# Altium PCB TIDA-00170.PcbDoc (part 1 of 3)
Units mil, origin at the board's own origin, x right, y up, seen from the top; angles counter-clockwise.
Board outline 3780 x 2000 mil, 4 copper layers (Top Layer, L2_GND-PLANE, L3_PWR-PLANE, Bottom Layer), stack 90 mil thick; 275 components, 132 nets, 768 pads, 262 vias.
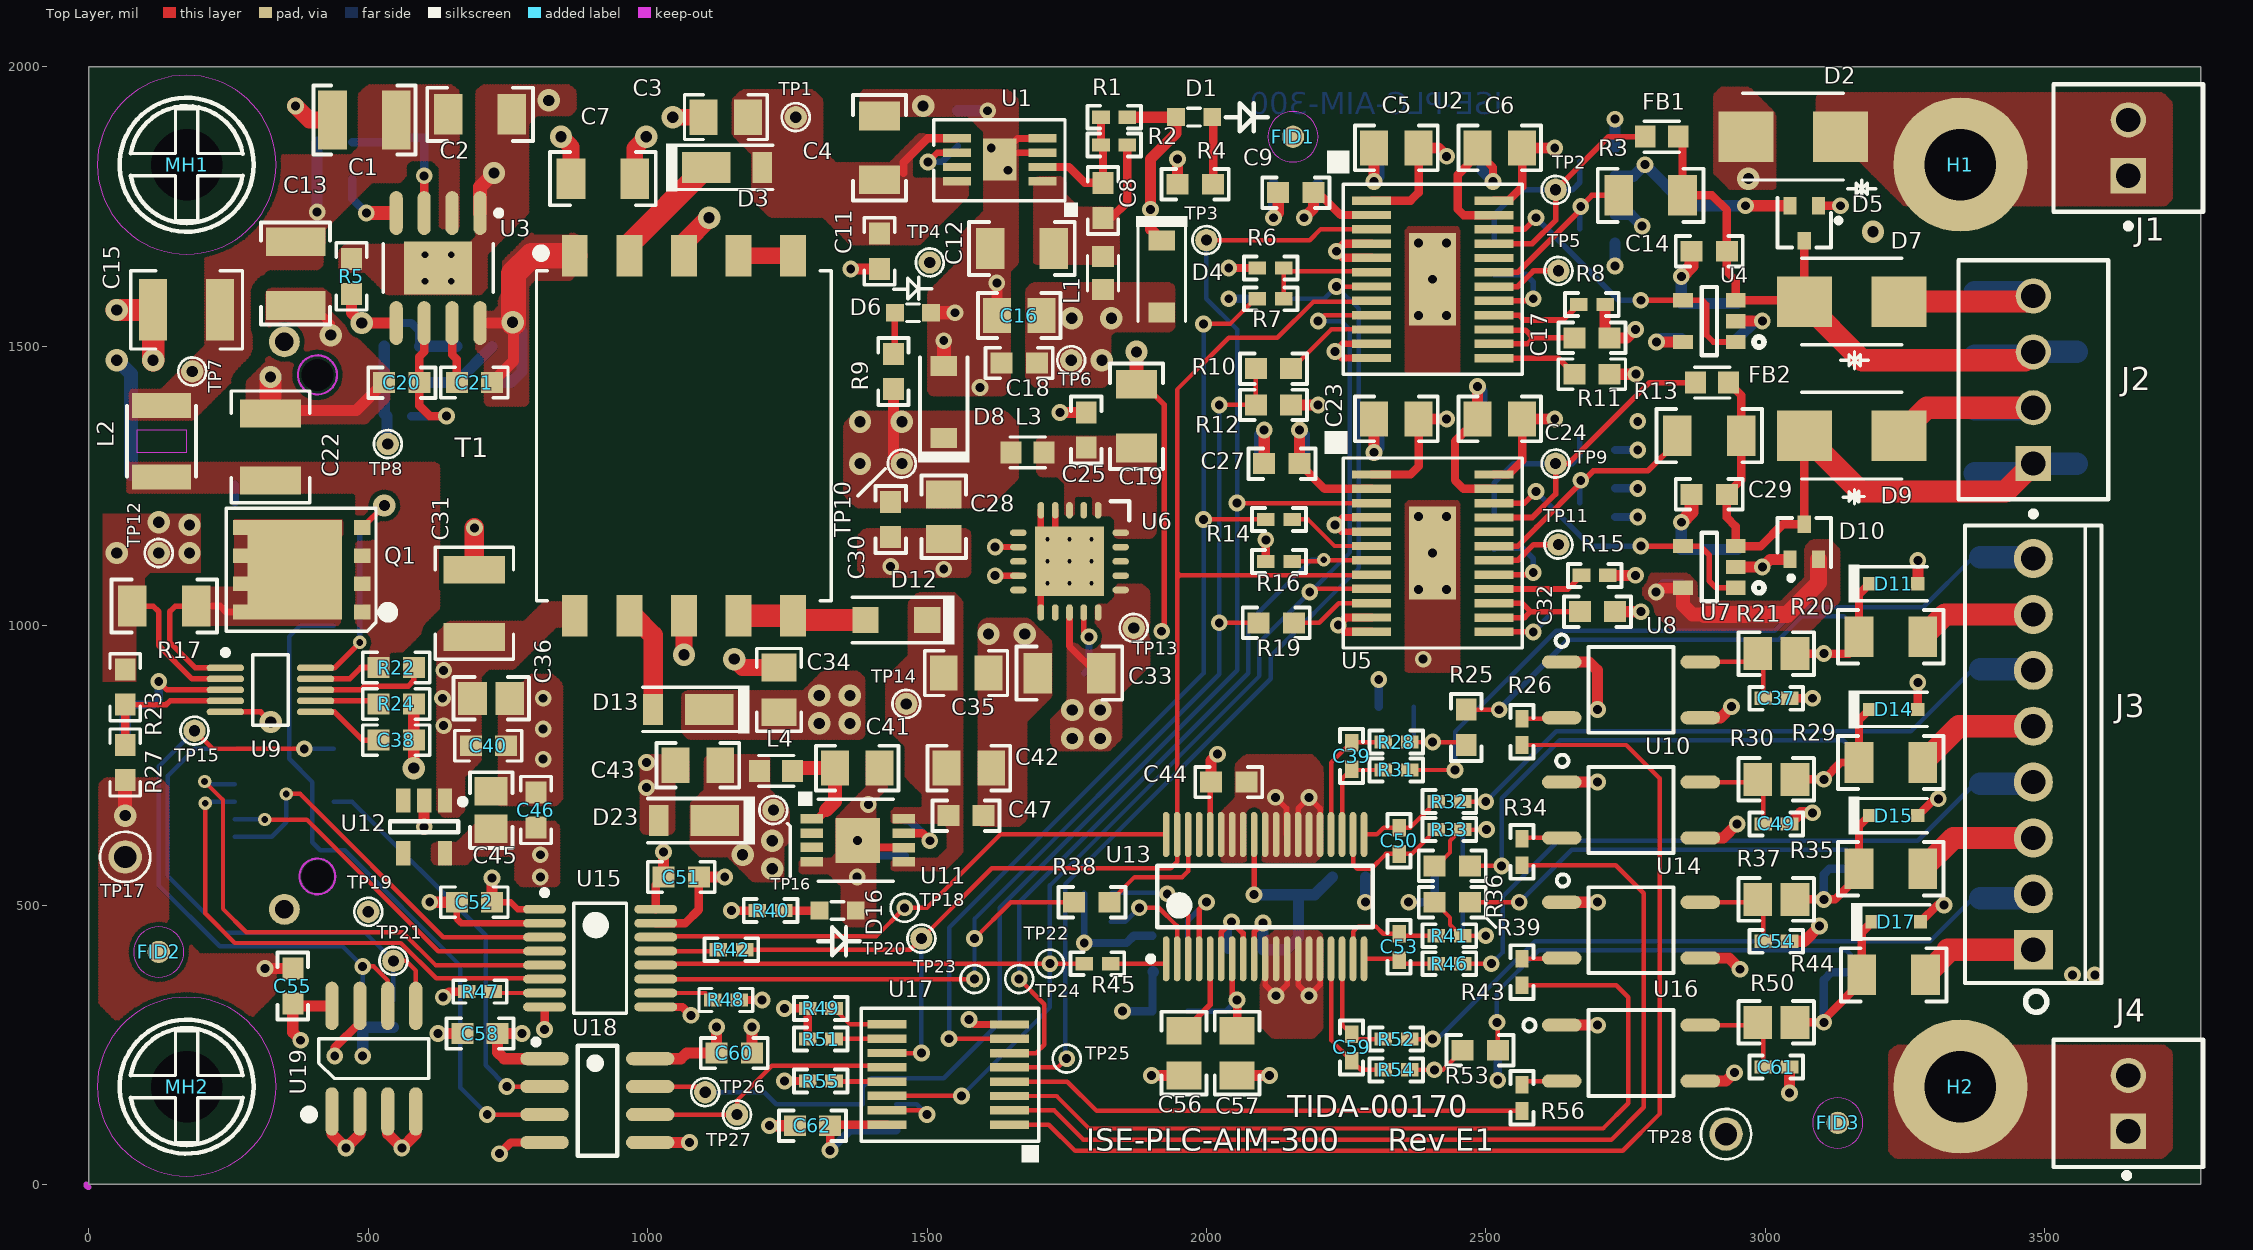
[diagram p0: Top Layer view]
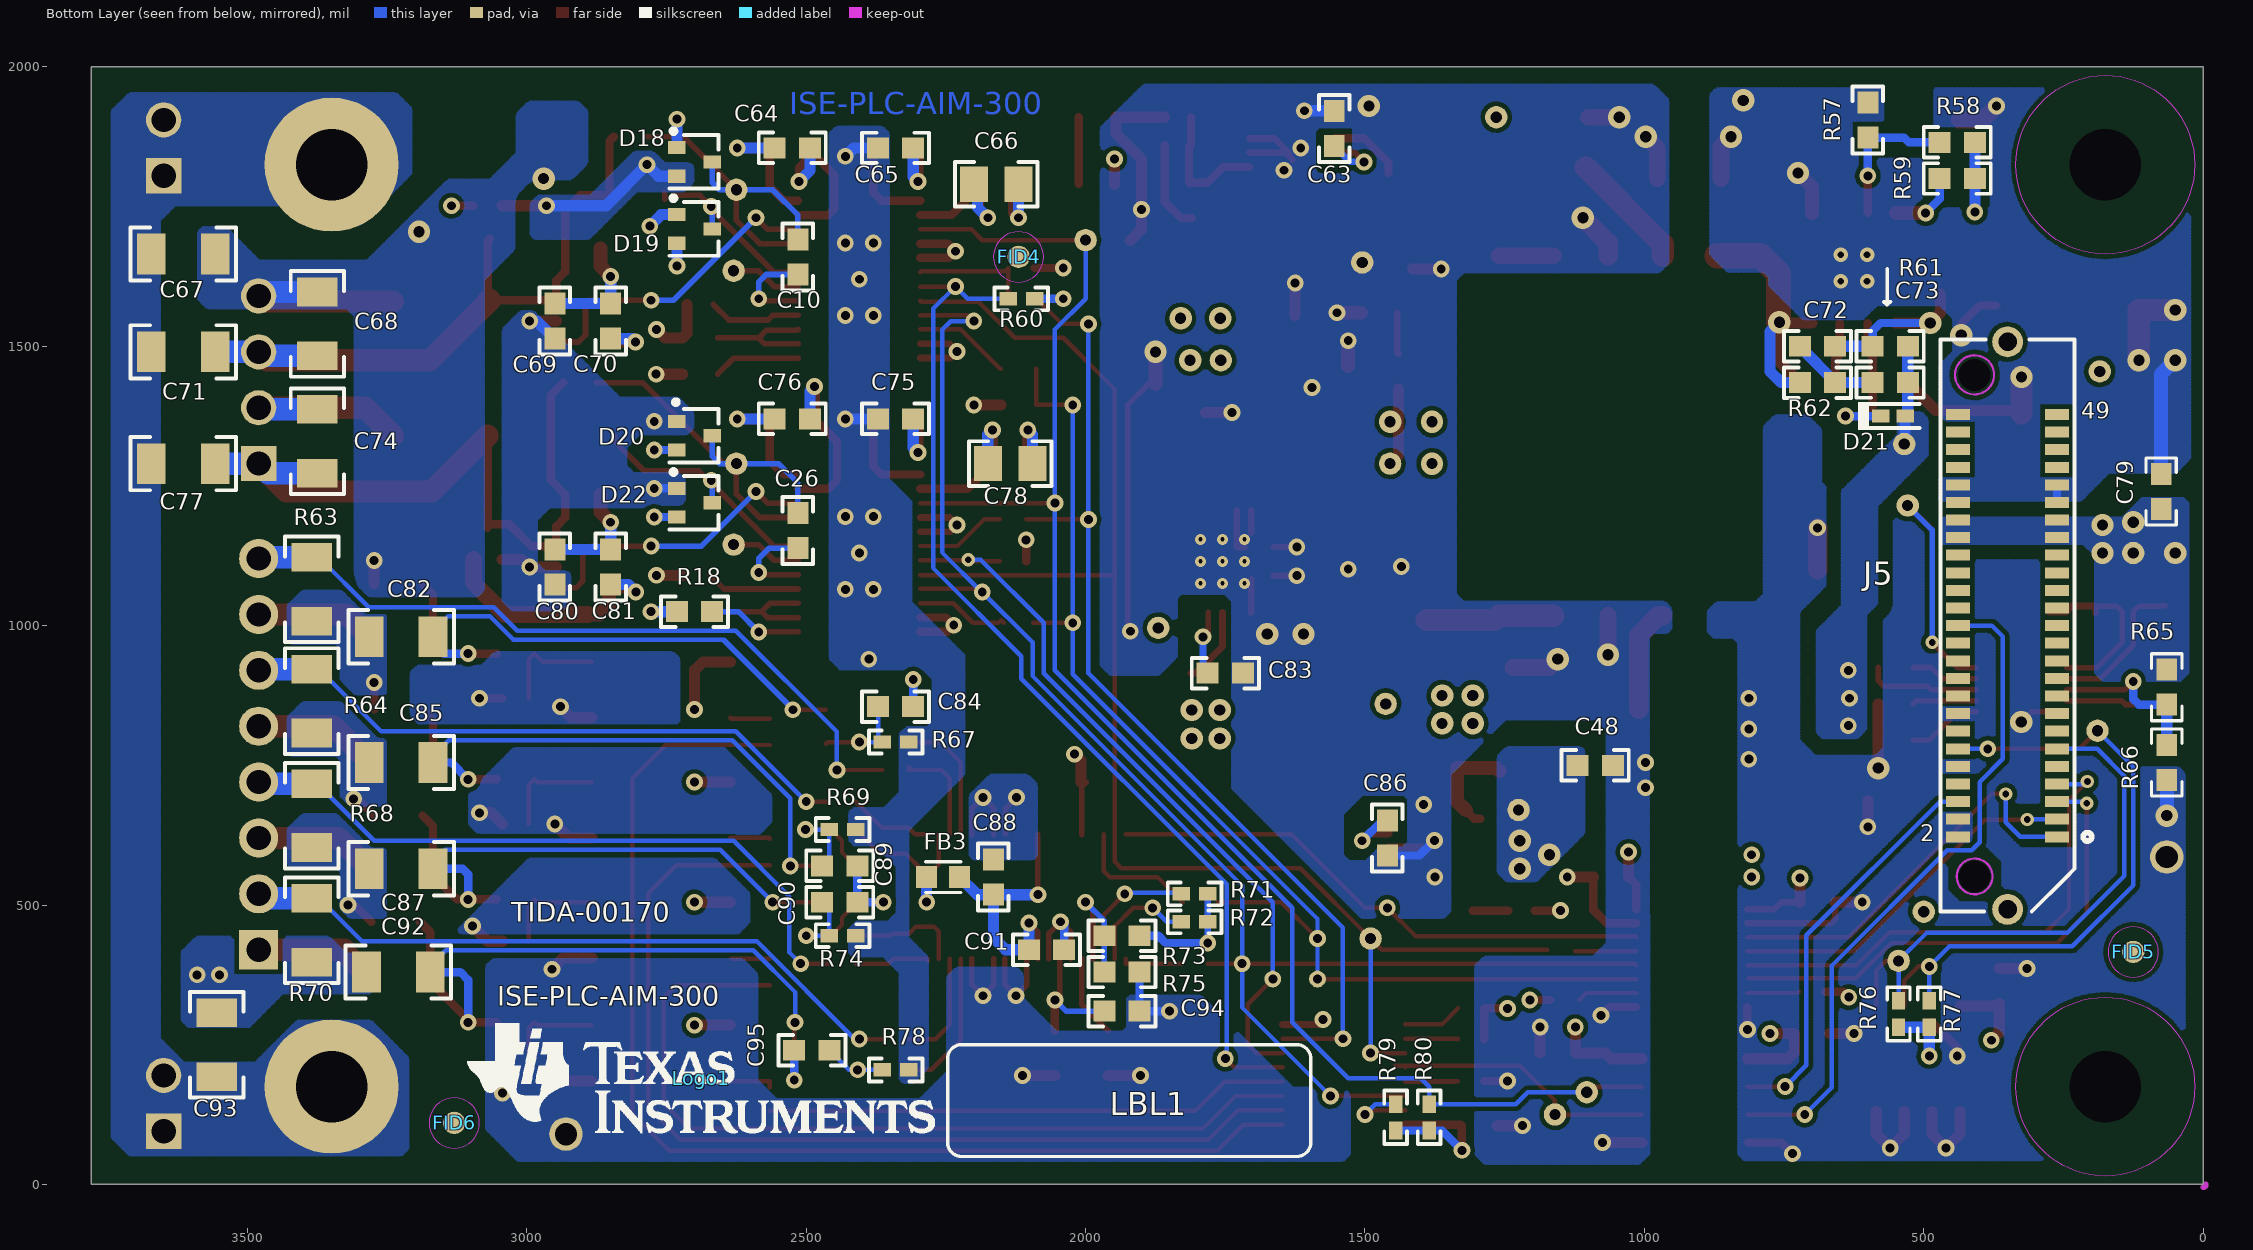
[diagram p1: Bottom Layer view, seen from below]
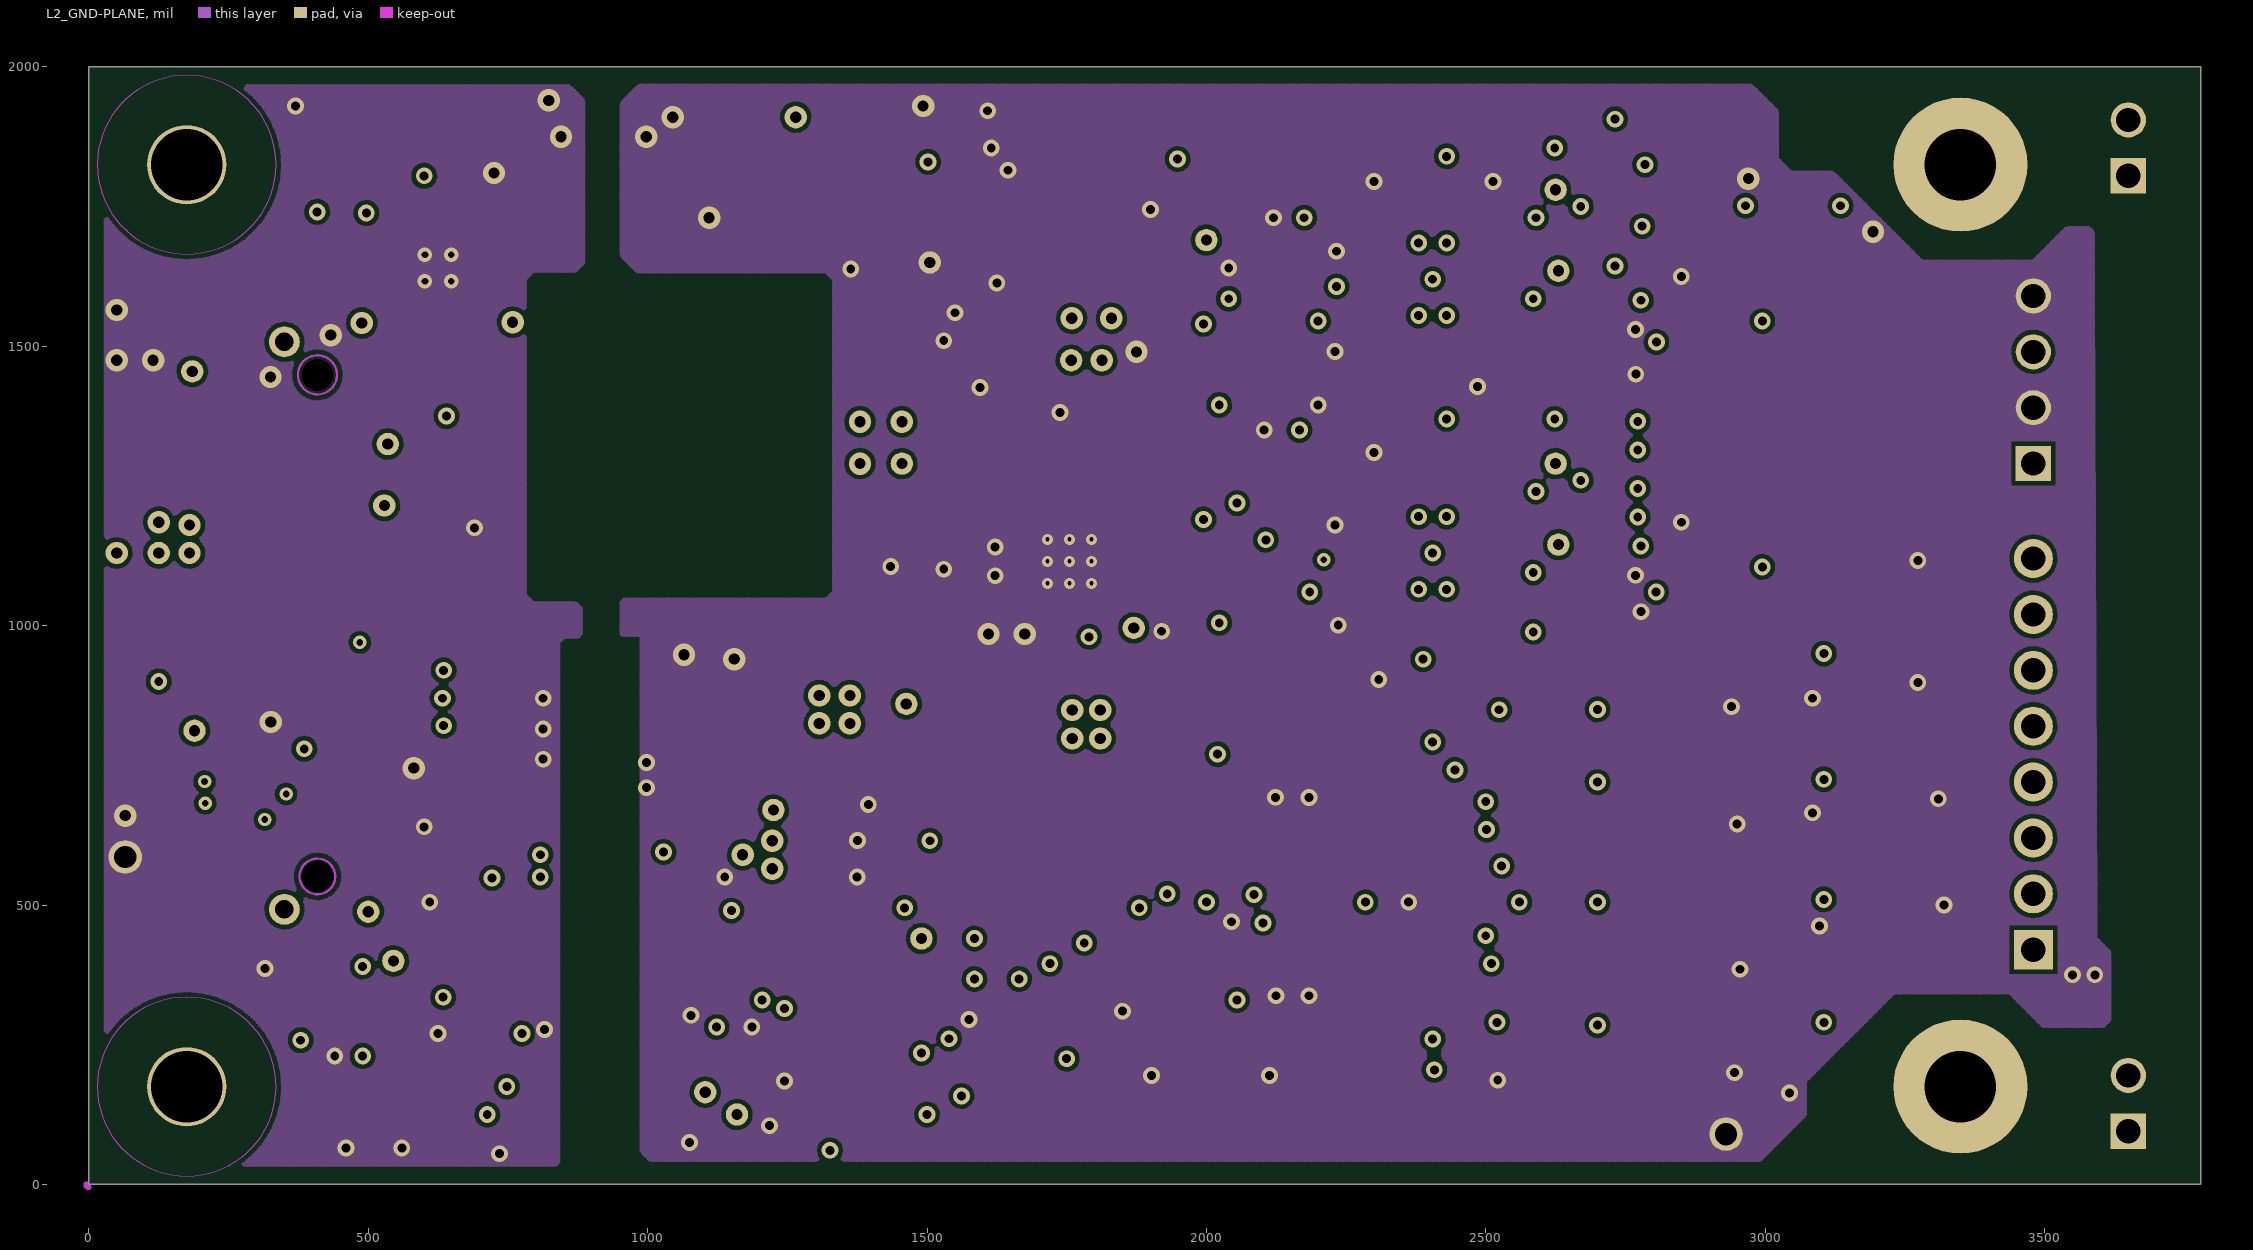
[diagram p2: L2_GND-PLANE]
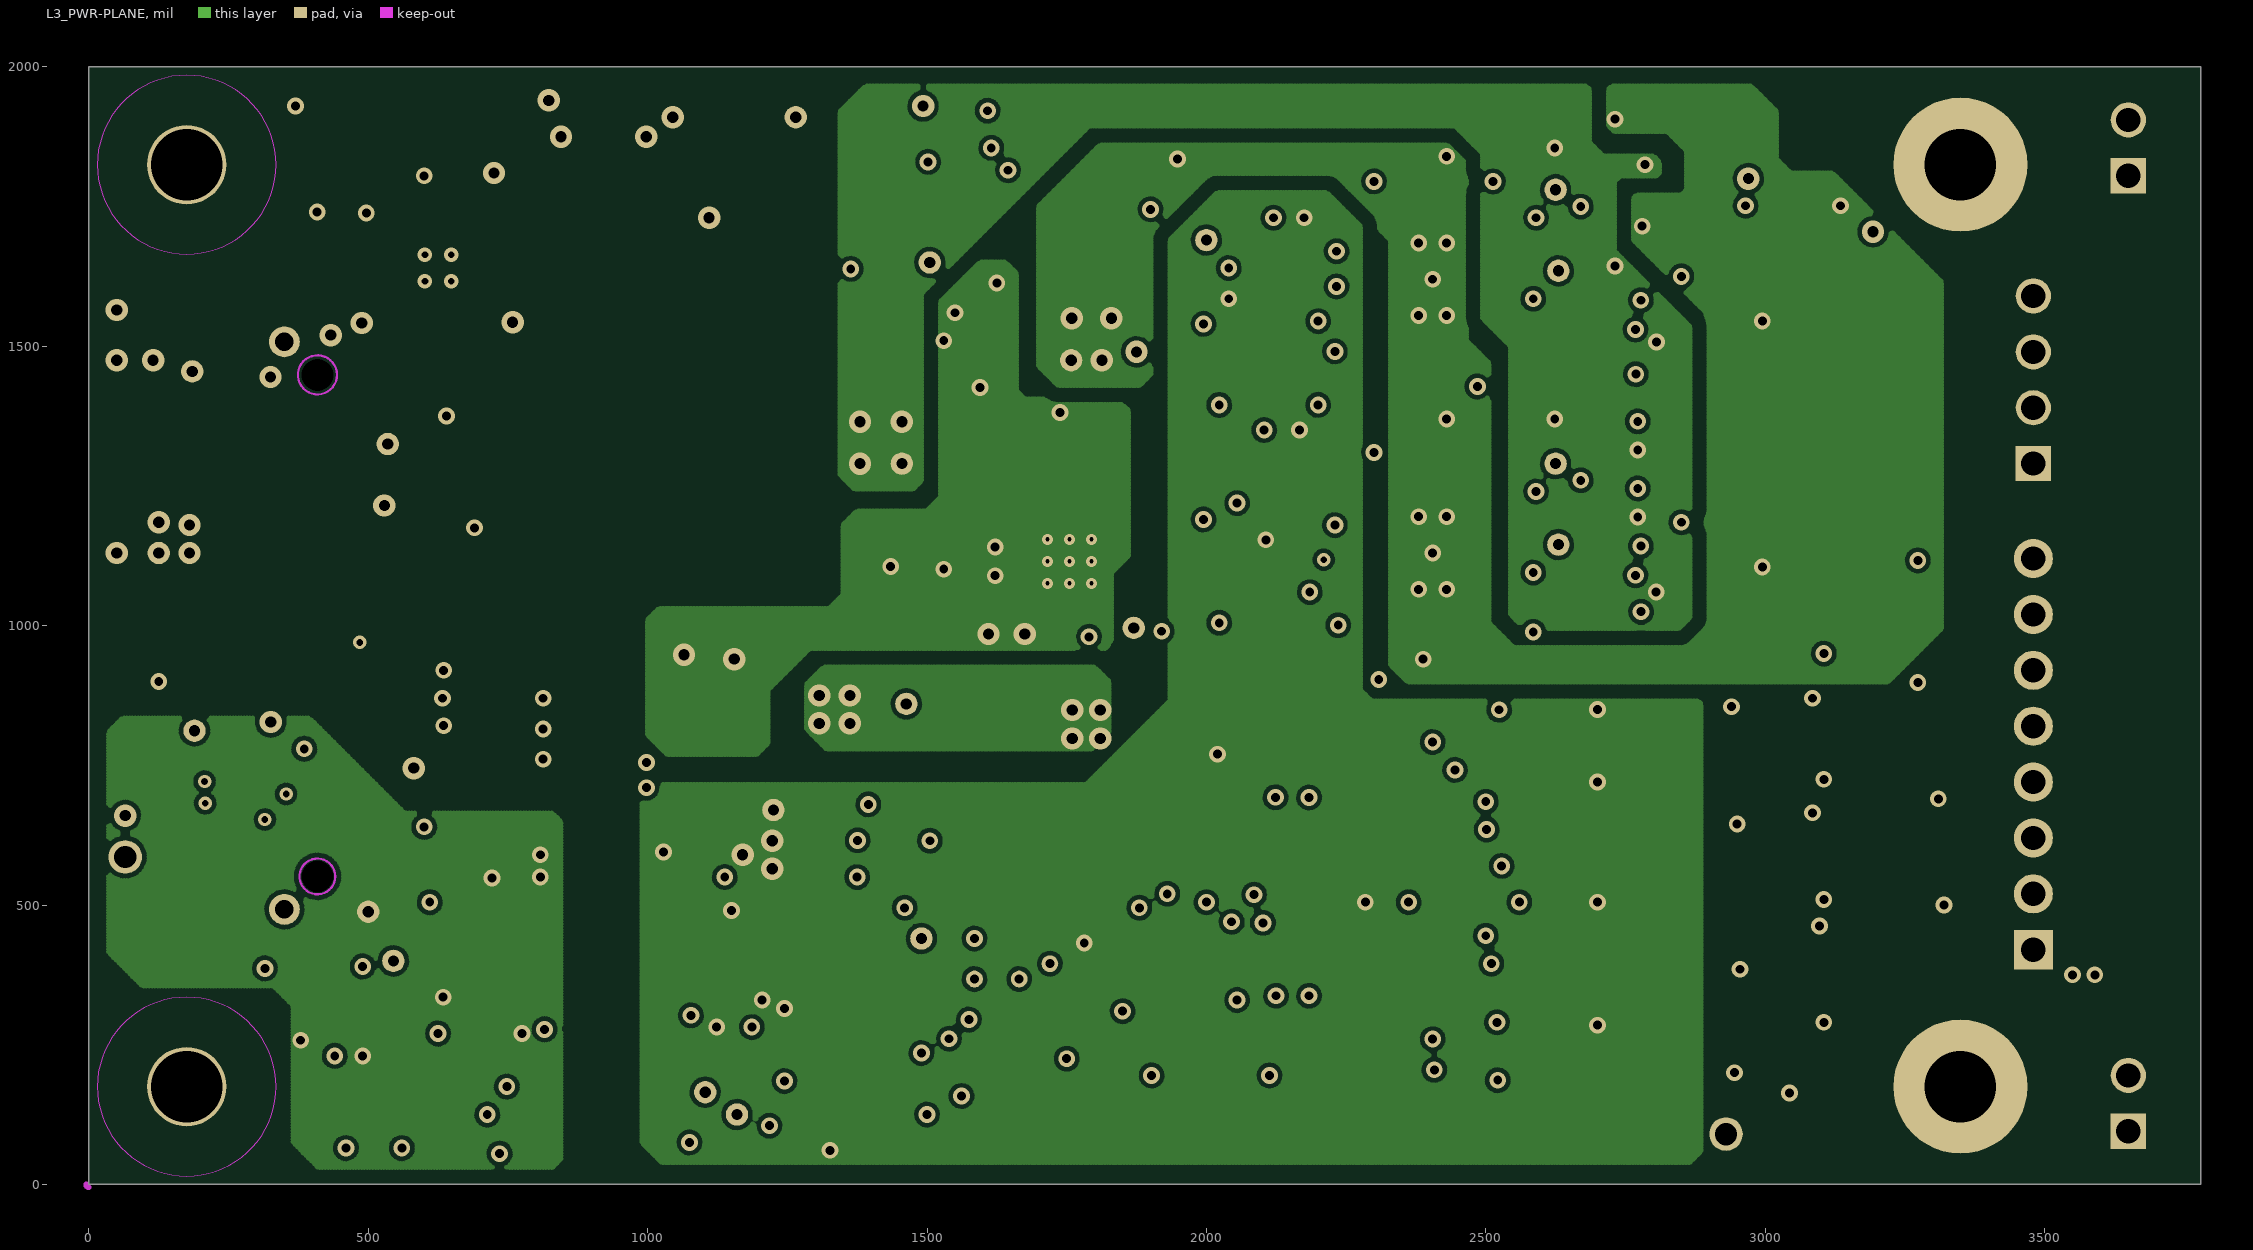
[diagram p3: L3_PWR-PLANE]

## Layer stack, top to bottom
Top Layer: signal copper 1.4
Dielectric: core 59.2, FR-4, Dk 4.8
L2_GND-PLANE: signal copper 1.4
Dielectric: prepreg 12.6, FR-4, Dk 4.8
L3_PWR-PLANE: signal copper 1.4
Dielectric: core 12.6, FR-4, Dk 4.8
Bottom Layer: signal copper 1.4

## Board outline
0,0 0,2000 3780,2000 3780,0

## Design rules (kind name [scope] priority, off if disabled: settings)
AcuteAngle [All] p1: minimum=4.50000000000000E+0001 checktracksonly=FALSE
AssemblyTestPointUsage [All] p1: valid=2
Clearance "U7 AND U9 Pad Class" [(InPadClass('Less Than 7.7')) vs (InPadClass('Less Than 7.7'))] p1: gap=7.8
Clearance "Clearance_Poly to Poly" [InPolygon vs InPolygon] p2: gap=25
Clearance "Clearance_VIA TO VIA" [IsVia vs IsVia] p3: gap=10
Clearance "Clearance_Via to SMD" [IsVia vs IsSMTPin] p4: gap=9
Clearance Clearance_BoardEdge_MountingHoles [OnCopper and InComponentClass('Mounting Holes') vs IsKeepOut] p5: gap=40
Clearance Clearance_Poly [InPolygon vs IsTrack and IsVia and IsSMTPin and IsThruPin] p6: gap=12
Clearance [All] p7: gap=8
ComponentClearance ComponentClearance_Logo [InComponentClass('Logo')] p1: gap=50 collisioncheckmode=3 verticalgap=10 showdistances=FALSE
ComponentClearance ComponentClearance_ScrewToNut [(HasFootprint('NY PMS 440 0025 PH')) vs (HasFootprint('Keystone_1902C'))] p2: gap=5 collisioncheckmode=3 verticalgap=10 showdistances=FALSE
ComponentClearance ComponentClearance_MountingHoles [InComponentClass('Mounting Holes')] p3: gap=250 collisioncheckmode=3 verticalgap=100000 showdistances=FALSE
ComponentClearance ComponentClearance_SmallPassives [HasFootprint('0201*') or HasFootprint('0402*') or HasFootprint('0508') or HasFootprint('0603*') or HasFootprint('0612') or HasFootprint('0805*') or HasFootprint('0815*') or HasFootprint('0830*') or HasFootprint('1206*') or HasFootprint('1210*') or HasFootprint('1808*') or HasFootprint('1812*') or HasFootprint('1825*') or HasFootprint('2010*') or HasFootprint('2220*') or HasFootprint('2225*') or HasFootprint('2512*') or HasFootprint('2728*') or HasFootprint('3518*') vs HasFootprint('0201*') or HasFootprint('0402*') or HasFootprint('0508') or HasFootprint('0603*') or HasFootprint('0612') or HasFootprint('0805*') or HasFootprint('0815*') or HasFootprint('0830*') or HasFootprint('1206*') or HasFootprint('1210*') or HasFootprint('1808*') or HasFootprint('1812*') or HasFootprint('1825*') or HasFootprint('2010*') or HasFootprint('2220*') or HasFootprint('2225*') or HasFootprint('2512*') or HasFootprint('2728*') or HasFootprint('3518*')] p4: gap=20 collisioncheckmode=3 verticalgap=10 showdistances=FALSE
ComponentClearance ComponentClearance_THtoSMT [IsThruComponent vs IsSMTComponent] p5: gap=100 collisioncheckmode=3 verticalgap=30 showdistances=FALSE
ComponentClearance ComponentClearance_THtoTH [IsThruComponent vs IsThruComponent] p6: gap=118.11 collisioncheckmode=3 verticalgap=30 showdistances=FALSE
ComponentClearance [All] p7: gap=40 collisioncheckmode=3 verticalgap=10 showdistances=FALSE
DiffPairsRouting [All] p1: maxlimit=100 minlimit=10 mostfreqgap=10 maxuncoupledlength=1000
FabricationTestPointUsage TestPointUsage [All] p1: valid=2 allowmultiple=FALSE
FabricationTestpoint Testpoint [All] p1: side=3 testpointundercomponent=TRUE minsize=40 maxsize=100 preferedsize=60 minholesize=0 maxholesize=40 preferedholesize=32 testpointgrid=1 allowsidetop=TRUE allowsidebottom=TRUE usegrid=TRUE gridtolerance=0.01
FanoutControl Fanout_LCC [IsLCC] p1: bgadir=Out bgaviamode=Centered fanoutstyle=Auto fanoutdirection=Alternating viagrid=1 // Fanout_LCC (Default Rule)
FanoutControl Fanout_BGA [IsBGA] p2: bgadir=Out bgaviamode=Centered fanoutstyle=Auto fanoutdirection=Alternating viagrid=1 // Fanout_BGA (Default Rule)
FanoutControl Fanout_Default [All] p4: bgadir=Out bgaviamode=Centered fanoutstyle=Auto fanoutdirection=Alternating viagrid=1 // Fanout_Default (Default Rule)
FanoutControl Fanout_Small [(CompPinCount < 5)] p5: bgadir=Out bgaviamode=Centered fanoutstyle=Auto fanoutdirection=OutThenIn viagrid=1 // Fanout_Small (Default Rule)
HoleSize [All] p1: absolutevalues=TRUE maxlimit=251 minlimit=7.8 maxpercent=80.000 minpercent=20.000
MinimumAnnularRing MinimumAnnularRing_ThermalPadVias [IsVia and InAnyComponent] p1: minimumring=5.91
MinimumAnnularRing [All] p2: minimumring=6
MinimumSolderMaskSliver MinimumSolderMaskSliver_Logo [InComponentClass('Logo') vs InComponentClass('Logo')] p1: minsoldermaskwidth=0.7
MinimumSolderMaskSliver [All] p2: minsoldermaskwidth=3.94
PlaneClearance [All] p1: clearance=16
PlaneConnect [All] p1: planeconnectstyle=Direct reliefexpansion=10 reliefentries=4 reliefconductorwidth=10 reliefairgap=10
PolygonConnect [All] p1: connectstyle=Direct reliefconductorwidth=10 reliefentries=4 polygonreliefangle="90 Angle" airgapwidth=10
RoutingVias RoutingVias_PWR [InNetClass('PWR')] p1: holewidth=20 width=40 viastyle="Through Hole" minholewidth=20 minwidth=40 maxholewidth=20 maxwidth=40
RoutingVias [InNetClass('All Nets')] p2: holewidth=16 width=30 viastyle="Through Hole" minholewidth=8 minwidth=20 maxholewidth=20 maxwidth=40
RoutingVias ThermalPadVias [IsVia and InAnyComponent] p3: holewidth=7.87 width=19.68 viastyle="Through Hole" minholewidth=7.87 minwidth=19.68 maxholewidth=12.99 maxwidth=23.62
SMDToCorner [All] p1: distance=30000
SilkToSilkClearance [All] p1: silktosilkclearance=5
SilkscreenOverComponentPads [All] p1 off: minsilkscreentomaskgap=5
SolderMaskExpansion [All] p1: expansion=2.5
Width Width_PWR [InNetClass('PWR')] p1: maxlimit=100 minlimit=8 preferedwidth=10
Width [All] p2: maxlimit=100 minlimit=6 preferedwidth=8 checkconnectedcopper=TRUE
13 further rules are at their usual default settings.

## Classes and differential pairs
pad class "Less Than 7.7": U9-1 U9-2 U9-3 U9-4 U9-5 U9-6 U9-7 U9-8 U9-9 U9-10 U13-1 U13-2 U13-3 U13-4 U13-5 U13-6 U13-7 U13-8 U13-9 U13-10 U13-11 U13-12 U13-13 U13-14 U13-15 U13-16 U13-17 U13-18 U13-19 U13-20 U13-21 U13-22 U13-23 U13-24 U13-25 U13-26 U13-27 U13-28 U13-29 U13-30 U13-31 U13-32 U13-33 U13-34 U13-35 U13-36 U13-37 U13-38
component class "Pg4 ISO Power Supply, I2C & SPI Isolators": C1 C2 C3 C7 C13 C15 C20 C21 C31 C34 C35 C36 C40 C45 C46 C51 C52 C58 C60 C62 C72 C73 D3 D12 D13 D21 L2 R5 R42 R47 R48 R49 R51 R55 R57 R58 R59 R61 R62 R79 T1 TP1 TP4 TP7 TP8 TP13 TP14 TP19 TP26 TP27 U3 U12 U15 U17 U18
component class "Pg3 Interboard conn, HS & EEPROM": C22 C38 C55 C79 J5 Q1 R17 R22 R23 R24 R27 R65 R66 R76 R77 TP12 TP15 TP17 TP21 U9 U19
component class "Pg6 ADC": C37 C39 C44 C49 C50 C53 C54 C56 C57 C59 C61 C67 C82 C84 C85 C87 C88 C89 C90 C91 C92 C93 C94 C95 D2 D11 D14 D15 D17 FB3 J1 J3 J4 R20 R21 R25 R26 R28 R29 R30 R31 R32 R33 R34 R35 R36 R37 R38 R39 R41 R43 R44 R45 R46 R50 R52 R53 R54 R56 R63 R64 R67 R68 R69 R70 R71 R72 R73 R74 R75 R78 TP18 TP23 TP28 U8 U10 U13 U14 U16
component class Logo: Logo1
component class "Pg9 Hardware": FID1 FID2 FID3 FID4 FID5 FID6 H1 H2 LBL1 Logo1 MH1 MH2 ZZ1 ZZ2 ZZ3 ZZ4
component class AssemblyNote: ZZ1 ZZ2 ZZ3 ZZ4
component class Label: LBL1
component class "Mounting Holes": H1 H2
component class "Pg5 LDO": C4 C8 C11 C12 C16 C18 C19 C25 C28 C30 C33 C41 C42 C43 C47 C48 C63 C83 C86 D1 D4 D6 D8 D16 D23 D25 L1 L3 L4 R1 R2 R4 R9 R40 TP6 TP10 TP16 U1 U6 U11
component class "Pg8 Analog Output": C5 C6 C9 C10 C14 C17 C23 C24 C26 C27 C29 C32 C64 C65 C66 C68 C69 C70 C71 C74 C75 C76 C77 C78 C80 C81 D5 D7 D9 D10 D18 D19 D20 D22 FB1 FB2 J2 R3 R6 R7 R8 R10 R11 R12 R13 R14 R15 R16 R18 R19 R60 R80 TP2 TP3 TP5 TP9 TP11 TP20 TP22 TP24 TP25 TP39 TP40 TP41 TP42 TP43 TP44 TP46 U2 U4 U5 U7

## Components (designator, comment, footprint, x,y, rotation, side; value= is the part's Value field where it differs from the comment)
C1 "GRM32ER72A225KA35L" 1210#1 493,1905 r0 top (schematic designator C10)
C2 "GRM31MR72A474KA35L" 1206 700,1915 r180 top (schematic designator C3)
C3 "GRM21BR71E225KA73L" 0805_HV 1140,1910 r0 top (schematic designator C24)
C4 "GRM31CR71H475KA12L" 1206 1415,1855 r90 top (schematic designator C112)
C5 "C2012X5R1H475K125AB" 0805_HV 2340,1855 r180 top (schematic designator C86)
C6 "C2012X5R1H475K125AB" 0805_HV 2525,1855 r0 top (schematic designator C87)
C7 "202R18W102KV4E" 1206 920,1800 r0 top (schematic designator C36)
C8 "06031C103JAT2A" 0603 1815,1761 r90 top (schematic designator C76)
C9 "06035C104KAT2A" 0603 2160,1775 r0 top (schematic designator C85)
C10 "GRM188R71H392KA01D" 0603 2515,1660 r270 bottom (schematic designator C93)
C11 "06035C104KAT2A" 0603 1415,1670 r90 top (schematic designator C18)
C12 "GRM31CR71E106KA12L" 1206 1670,1675 r180 top (schematic designator C33)
C13 "GRM32ER71H106KA12L" 1210#1 370,1630 r270 top (schematic designator C136)
C14 "06035C104KAT2A" 0603 2900,1670 r180 top (schematic designator C90)
C15 "GRM32ER72A225KA35L" 1210#2 175,1565 r180 top (schematic designator C88)
C16 "C2012X5R1H475K125AB" 0805_HV 1665,1555 r0 top (schematic designator C21)
C17 "06035C104KAT2A" 0603 2690,1515 r180 top (schematic designator C94)
C18 "06035C104KAT2A" 0603 1665,1470 r0 top (schematic designator C77)
C19 "GRM31CR71E106KA12L" 1206 1875,1375 r90 top (schematic designator C11)
C20 "GRM188R61H105KAALD" 0603 560,1435 r180 top (schematic designator C8)
C21 "06031C103JAT2A" 0603 690,1435 r0 top (schematic designator C4)
C22 "GRM32ER72A225KA35L" 1210#2 325,1320 r270 top (schematic designator C44)
C23 "C2012X5R1H475K125AB" 0805_HV 2340,1370 r0 top (schematic designator C95)
C24 "C2012X5R1H475K125AB" 0805_HV 2525,1370 r180 top (schematic designator C97)
C25 "06035C104KAT2A" 0603 1785,1350 r270 top (schematic designator C91)
C26 "GRM188R71H392KA01D" 0603 2515,1170 r270 bottom (schematic designator C99)
C27 "06035C104KAT2A" 0603 2135,1290 r0 top (schematic designator C78)
C28 "C2012X5R1H475K125AB" 0805_HV 1530,1195 r270 top (schematic designator C9)
C29 "06035C104KAT2A" 0603 2900,1235 r180 top (schematic designator C79)
C30 "06035C104KAT2A" 0603 1435,1190 r90 top (schematic designator C13)
C31 "GMK325AB7106MM-T" 1210#2 690,1040 r270 top (schematic designator C96)
C32 "06035C104KAT2A" 0603 2700,1025 r180 top (schematic designator C100)
C33 "GRM31CR71H475KA12L" 1206 1755,915 r180 top (schematic designator C40)
C34 "GRM21BR71E225KA73L" 0805_HV 1235,885 r90 top (schematic designator C6)
C35 "GRM21BR71E225KA73L" 0805_HV 1570,915 r0 top (schematic designator C90)
C36 "08055C105KAT2A" 0805 720,870 r0 top (schematic designator C17)
C37 "C1005X7R1H102M" 0402 3020,870 r0 top (schematic designator C25)
C38 "UMK107ABJ474KA-T" 0603 550,795 r0 top (schematic designator C78)
C39 "GRM155R71H103KA88D" 0402 2260,766.65 r270 top (schematic designator C55)
C40 "C0603C104K5RACTU" 0603 715,785 r0 top (schematic designator C20)
C41 "GRM21BR61C226ME44" 0805_HV 1375,745 r0 top (schematic designator C26)
C42 "GRM21BR61C226ME44" 0805_HV 1575,745 r0 top (schematic designator C114)
C43 "C2012X5R1H475K125AB" 0805_HV 1090,750 r180 top (schematic designator C27)
C44 "C1608X5R1E106M080AC" 0603 2040,720 r0 top (schematic designator C131)
C45 "0805YD106MAT2A" 0805 720,670 r90 top (schematic designator C105)
C46 "C0603C104K5RACTU" 0603 800,670 r90 top (schematic designator C23)
C47 "06035C104KAT2A" 0603 1570,660 r180 top (schematic designator C1)
C48 "06035C104KAT2A" 0603 1088,750 r0 bottom (schematic designator C96)
C49 "C1005X7R1H102M" 0402 3020,645 r0 top (schematic designator C7)
C50 "GRM155R71H103KA88D" 0402 2345,615 r90 top (schematic designator C113)
C51 "C0603C104K5RACTU" 0603 1060,550 r0 top (schematic designator C68)
C52 "C0603C104K5RACTU" 0603 690,505 r0 top (schematic designator C106)
C53 "GRM155R71H103KA88D" 0402 2345,425 r270 top (schematic designator C118)
C54 "C1005X7R1H102M" 0402 3020,435 r0 top (schematic designator C14)
C55 "C0603C104K5RACTU" 0603 365,355 r270 top (schematic designator C29)
C56 "0805YD106MAT2A" 0805_HV 1960,235 r270 top (schematic designator C119)
C57 "C2012X5R1C226K125AC" 0805_HV 2055,235 r90 top (schematic designator C120)
C58 "C0603C104K5RACTU" 0603 700,270 r0 top (schematic designator C133)
C59 "GRM155R71H103KA88D" 0402 2260,245 r90 top (schematic designator C117)
C60 "C0603C104K5RACTU" 0603 1155,235 r0 top (schematic designator C134)
C61 "C1005X7R1H102M" 0402 3020,210 r0 top (schematic designator C5)
C62 "C0603C104K5RACTU" 0603 1295,105 r0 top (schematic designator C135)
C63 "06031C103JAT2A" 0603 1555,1890 r90 bottom (schematic designator C82)
C64 "06035C104KAT2A" 0603 2525,1855 r180 bottom (schematic designator C84)
C65 "06035C104KAT2A" 0603 2340,1855 r0 bottom (schematic designator C83)
C66 "C2012X5R1H475K125AB" 0805_HV 2160,1790 r0 bottom (schematic designator C89)
C67 "202R18W102KV4E" 1206 3615,1665 r0 bottom (schematic designator C30)
C68 "202R18W102KV4E" 1206 3375,1540 r90 bottom (schematic designator C93)
C69 "06035C104KAT2A" 0603 2950,1545 r90 bottom (schematic designator C92)
C70 "06035C104KAT2A" 0603 2850,1545 r90 bottom (schematic designator C91)
C71 "202R18W102KV4E" 1206 3615,1490 r0 bottom (schematic designator C110)
C72 "GRM188R72A104KA35D" 0603 690,1500 r180 bottom (schematic designator C94)
C73 "06031C332JAT2A" 0603 560,1435 r180 bottom (schematic designator C92)
C74 "202R18W102KV4E" 1206 3375,1330 r90 bottom (schematic designator C22)
C75 "06035C104KAT2A" 0603 2340,1370 r180 bottom
C76 "06035C104KAT2A" 0603 2525,1370 r0 bottom (schematic designator C74)
C77 "202R18W102KV4E" 1206 3615,1290 r0 bottom (schematic designator C35)
C78 "C2012X5R1H475K125AB" 0805_HV 2135,1290 r180 bottom (schematic designator C98)
C79 "06031C102MAT2A" 0603 75,1240 r90 bottom (schematic designator C70)
C80 "06035C104KAT2A" 0603 2950,1105 r270 bottom
C81 "06035C104KAT2A" 0603 2850,1105 r270 bottom
C82 "GRM3195C1H273JA01D" 1206 3225,980 r0 bottom (schematic designator C107)
C83 "C1608X7R1E105K080AB" 0603 1750,915 r180 bottom (schematic designator C32)
C84 "06031C272JAT2A" 0603 2340,855 r180 bottom (schematic designator C108)
C85 "GRM3195C1H273JA01D" 1206 3225,755 r0 bottom (schematic designator C19)
C86 "06031C102JAT2A" 0603 1460,620 r270 bottom (schematic designator C88)
C87 "GRM3195C1H273JA01D" 1206 3225,565 r0 bottom (schematic designator C16)
C88 "EMK107BBJ106MA-T" 0603 2165,550 r90 bottom (schematic designator C122)
C89 "06031C272JAT2A" 0603 2440,570 r180 bottom (schematic designator C28)
C90 "06031C272JAT2A" 0603 2440,505 r180 bottom (schematic designator C15)
C91 "EMK107BBJ106MA-T" 0603 2070,420 r180 bottom (schematic designator C109)
C92 "GRM3195C1H273JA01D" 1206 3230,380 r0 bottom (schematic designator C12)
C93 "202R18W102KV4E" 1206 3555,250 r270 bottom (schematic designator C34)
C94 "EMK107B7105KA-T" 0603 1935,310 r0 bottom (schematic designator C121)
C95 "06031C272JAT2A" 0603 2490,240 r0 bottom (schematic designator C2)
D1 "LED_LG L29K-G2J1-24-Z" LED0603AA 1978,1910 r180 top (schematic designator D15)
D2 "SMBJ18CA" DIO_SMB_BIAAAA 3050,1875 r0 top (schematic designator D23)
D3 "DFLS1200-7" powerDI123 1155,1820 r0 top (schematic designator D4)
D4 "DZ2W18000L" SOD-123 1920,1625 r270 top (schematic designator D6)
D5 "DESD1P0RFW-7" SOT-323 3070,1720 r270 top (schematic designator D20)
D6 "LED_LG L29K-G2J1-24-Z" LED0603AA 1475,1560 r180 top (schematic designator D2)
D7 "SMBJ18CA" DIO_SMB_BIAAAA 3155,1580 r0 top (schematic designator D19)
D8 "DZ2W18000L" SOD-123 1530,1400 r90 top (schematic designator D3)
D9 "SMBJ18CA" DIO_SMB_BIAAAA 3155,1340 r0 top (schematic designator D18)
D10 "DESD1P0RFW-7" SOT-323 3070,1150 r90 top (schematic designator D7)
D11 "CDSOD323-T12C" sod-323 3230,1075 r0 top (schematic designator D29)
D12 "PMEG6010CEH,115" SOD-123F 1445,1010 r180 top
D13 "DFLS1200-7" powerDI123 1060,850 r180 top (schematic designator D1)
D14 "CDSOD323-T12C" sod-323 3230,850 r0 top (schematic designator D28)
D15 "CDSOD323-T12C" sod-323 3230,660 r0 top (schematic designator D14)
D16 "LED_LG L29K-G2J1-24-Z" LED0603AA 1340,490 r180 top (schematic designator D25)
D17 "CDSOD323-T12C" sod-323 3235,470 r0 top (schematic designator D11)
D18 "DESD1P0RFW-7" SOT-323 2700,1830 r180 bottom (schematic designator D21)
D19 "DESD1P0RFW-7" SOT-323 2700,1710 r180 bottom (schematic designator D23)
D20 "DESD1P0RFW-7" SOT-323 2700,1340 r180 bottom (schematic designator D16)
D21 "SDM10U45-7-F" SOD-523 555,1375 r180 bottom (schematic designator D13)
D22 "DESD1P0RFW-7" SOT-323 2700,1220 r180 bottom (schematic designator D24)
D23 "PTZTE255.6B" powerDI123 1070,651 r180 top
FB1 "1000 OHM" FB0603 2815,1875 r180 top (schematic designator FB3)
FB2 "1000 OHM" FB0603 2905,1435 r180 top (schematic designator FB3)
FB3 "1000 OHM" FB0603 2255,550 r180 bottom (schematic designator FB1)
FID1 "Fiducial40_80" FID_TOP_40_80BA 2155,1875 r90 top (schematic designator FID5)
FID2 "Fiducial40_80" FID_TOP_40_80BA 125,416 r90 top (schematic designator FID4)
FID3 "Fiducial40_80" FID_TOP_40_80BA 3130,110 r0 top
FID4 "Fiducial40_80" FID_TOP_40_80BA 2120,1660 r180 bottom (schematic designator FID6)
FID5 "Fiducial40_80" FID_TOP_40_80BA 125,416 r90 bottom (schematic designator FID1)
FID6 "Fiducial40_80" FID_TOP_40_80BA 3130,110 r90 bottom (schematic designator FID2)
H1 "NY PMS 440 0025 PH" "NY PMS 440 0025 PH" 3349.53,1825 r0 top (schematic designator H2)
H2 "NY PMS 440 0025 PH" "NY PMS 440 0025 PH" 3349.53,175 r0 top (schematic designator H1)
J1 "282834-2" TEC_282834-2 3650,1855 r90 top (schematic designator J9)
J2 "282834-4" TEC_282834-4 3480,1440 r90 top (schematic designator J5)
J3 "1725711" CONN_1725711 3480,770 r90 top (schematic designator J1)
J4 "282834-2" TEC_282834-2 3650,145 r90 top (schematic designator J2)
J5 "ERF8-025-05.0-L-DV-K-TR" CONN_ERF8-025-05_0-L-DV-L-TR 350,1000 r270 bottom locked (schematic designator J10)
L1 "1000 OHM" FB0603 1815,1631 r270 top (schematic designator L2)
L2 "3.3µH" IND_B82422H 130,1330 r90 top (schematic designator L1)
L3 "1000 OHM" FB0603 1680,1310 r180 top
L4 "1000 OHM" FB0603 1230,740 r180 top
LBL1 "Size: 0.65\" x 0.20 \"" Label_650x200 1922,150 r180 bottom
Logo1 "Texas Instruments" TI_Stacked_SolderMask_Small 2688,190 r180 bottom
MH1 "MH 3.2MM" MH3.2_H5_W6_KO8_STARHEAD 175,1825 r0 top
MH2 "MH 3.2MM" MH3.2_H5_W6_KO8_STARHEAD 175,175 r0 top (schematic designator MH3)
Q1 "CSD18537NQ5A" TRANS_NexFET_Q5A 380,1100 r180 top
R1 "TNPW04029K42BEED" 0402 1835,1910 r0 top (schematic designator R30)
R2 "CRCW0402110KFKED" 0402 1835,1860 r180 top (schematic designator R50)
R3 "CRCW120610R0JNEA" 1206 2795,1770 r180 top (schematic designator R79)
R4 "CRCW06034K70JNEA" 0603 1980,1790 r0 top (schematic designator R145)
R5 "RC0603FR-0727KL" 0603 470,1625 r270 top (schematic designator R7)
R6 "CRCW04020000Z0ED" 0402 2115,1640 r180 top (schematic designator R34)
R7 "CRCW04020000Z0ED" 0402 2115,1585 r0 top (schematic designator R61)
R8 "CRCW04020000Z0ED" 0402 2690,1575 r0 top (schematic designator R110)
R9 "CRCW06034K70JNEA" 0603 1440,1455 r90 top (schematic designator R150)
R10 "CRCW060310R0FKEA" 0603 2120,1460 r0 top (schematic designator R107)
R11 "RT0603BRB0715KL" 0603 2690,1450 r0 top (schematic designator R27)
R12 "CRCW06031K00FKEA" 0603 2120,1395 r180 top (schematic designator R42)
R13 "CRCW120610R0JNEA" 1206 2900,1340 r180 top (schematic designator R102)
R14 "CRCW04020000Z0ED" 0402 2130,1190 r0 top (schematic designator R33)
R15 "CRCW04020000Z0ED" 0402 2695,1090 r0 top (schematic designator R26)
R16 "CRCW040210K0JNED" 0402 2130,1115 r180 top (schematic designator R128)
R17 "PRL1632-R020-F-T1" 1206 135,1035 r0 top (schematic designator R45)
R18 "RT0603BRB0715KL" 0603 2700,1025 r0 bottom (schematic designator R101)
R19 "CRCW060310R0FKEA" 0603 2125,1005 r0 top (schematic designator R46)
R20 "MMA02040C1000FB300" 1206 3225,980 r180 top (schematic designator R100)
R21 "RG2012P-201-B-T5" 0805 3020,950 r0 top
R22 "CRCW060310K0JNEA" 0603 550,925 r180 top (schematic designator R58)
R23 "CRCW060395K3FKEA" 0603 65,890 r90 top (schematic designator R93)
R24 "RG1608P-563-B-T5" 0603 550,860 r180 top (schematic designator R69)
R25 "CRCW06031K00FKEA" 0603 2465,818 r270 top (schematic designator R101)
R26 "CRCW0402680RJNED" 0402 2565,810 r90 top (schematic designator R24)
R27 "CRCW06037K15FKEA" 0603 65,755 r90 top (schematic designator R67)
R28 "CRCW04020000Z0ED" 0402 2340,791.65 r0 top (schematic designator R108)
R29 "MMA02040C1000FB300" 1206 3225,755 r180 top (schematic designator R86)
R30 "RG2012P-201-B-T5" 0805 3020,725 r0 top (schematic designator R9)
R31 "CRCW04021K10FKED" 0402 2340,741.65 r0 top (schematic designator R112)
R32 "CRCW04021K10FKED" 0402 2435,685 r0 top (schematic designator R114)
R33 "CRCW04020000Z0ED" 0402 2435,635 r0 top (schematic designator R111)
R34 "CRCW0402680RJNED" 0402 2565,595 r90 top (schematic designator R15)
R35 "MMA02040C1000FB300" 1206 3225,565 r180 top (schematic designator R84)
R36 "CRCW06031K00FKEA" 0603 2440,570 r180 top (schematic designator R19)
R37 "RG2012P-201-B-T5" 0805 3020,510 r0 top (schematic designator R17)
R38 "CRCW060310R0FKEA" 0603 1795,505 r180 top (schematic designator R142)
R39 "CRCW06031K00FKEA" 0603 2440,505 r180 top (schematic designator R13)
R40 "CRCW04021K20JNED" 0402 1220,490 r0 top (schematic designator R130)
R41 "CRCW04020000Z0ED" 0402 2435,445 r180 top (schematic designator R120)
R42 "RC0402JR-070RL" 0402 1150,420 r0 top (schematic designator R151)
R43 "CRCW0402680RJNED" 0402 2565,380 r90 top (schematic designator R23)
R44 "MMA02040C1000FB300" 1206 3230,375 r180 top (schematic designator R82)
R45 "CRCW040249R9FKED" 0402 1805,395 r0 top (schematic designator R35)
R46 "CRCW04021K10FKED" 0402 2435,395 r180 top (schematic designator R125)
R47 "CRCW040210K0JNED" 0402 700,345 r0 top (schematic designator R36)
R48 "CRCW040210K0JNED" 0402 1140,330 r0 top (schematic designator R32)
R49 "CRCW040210K0JNED" 0402 1310,315 r0 top (schematic designator R37)
R50 "RG2012P-201-B-T5" 0805 3020,290 r0 top (schematic designator R8)
R51 "CRCW040210K0JNED" 0402 1310,260 r0 top (schematic designator R2)
R52 "CRCW04021K10FKED" 0402 2340,260 r180 top (schematic designator R124)
R53 "CRCW06031K00FKEA" 0603 2490,240 r180 top (schematic designator R4)
R54 "CRCW04020000Z0ED" 0402 2340,205 r180 top (schematic designator R119)
R55 "CRCW040210K0JNED" 0402 1310,185 r0 top (schematic designator R1)
R56 "CRCW0402680RJNED" 0402 2565,155 r90 top (schematic designator R14)
R57 "RC0603FR-074K87L" 0603 600,1905 r270 bottom (schematic designator R81)
R58 "RT0603BRD0760K4L" 0603 440,1865 r180 bottom (schematic designator R80)
R59 "RC0603FR-0791KL" 0603 440,1800 r180 bottom (schematic designator R6)
R60 "CRCW040210K0JNED" 0402 2115,1585 r180 bottom (schematic designator R157)
R61 "RT0603BRD07189KL" 0603 560,1500 r180 bottom (schematic designator R83)
R62 "RT0603BRD0756K2L" 0603 690,1435 r0 bottom (schematic designator R77)
R63 "CRCW12060000Z0EAHP" 1206 3385,1065 r90 bottom (schematic designator R113)
R64 "CRCW12060000Z0EAHP" 1206 3385,865 r90 bottom (schematic designator R115)
R65 "CRCW060371K5FKEA" 0603 65,890 r90 bottom (schematic designator R94)
R66 "CRCW060314K3FKEA" 0603 65,755 r90 bottom (schematic designator R68)
R67 "CRCW040210M0FKED" 0402 2340,791.65 r0 bottom (schematic designator R102)
R68 "CRCW12060000Z0EAHP" 1206 3385,660 r90 bottom (schematic designator R44)
R69 "CRCW040210M0FKED" 0402 2435,635 r0 bottom (schematic designator R18)
R70 "CRCW12060000Z0EAHP" 1206 3385,455 r90 bottom (schematic designator R129)
R71 "CRCW040247K0JNED" 0402 1805,520 r0 bottom (schematic designator R132)
R72 "CRCW040247K0JNED" 0402 1805,470 r0 bottom (schematic designator R131)
R73 "RT0603BRD0747KL" 0603 1935,445 r0 bottom (schematic designator R133)
R74 "CRCW040210M0FKED" 0402 2435,445 r0 bottom (schematic designator R16)
R75 "RT0603BRD0747KL" 0603 1935,380 r180 bottom (schematic designator R158)
R76 "CRCW04021K50JNED" 0402 545,305 r90 bottom (schematic designator R99)
R77 "CRCW04021K50JNED" 0402 490,305 r90 bottom (schematic designator R97)
R78 "CRCW040210M0FKED" 0402 2340,205 r0 bottom (schematic designator R3)
R79 "CRCW040210K0JNED" 0402 1445,120 r270 bottom (schematic designator R38)
R80 "CRCW040210K0JNED" 0402 1385,120 r270 bottom (schematic designator R41)
T1 "750342178" WURTH_750313995 1065,1340 r0 top locked
TP1 "TP1_PD40_D0.5_S50" TP1_PD40_D0.5_S50#1 1265,1910 r0 top (schematic designator TP4)
TP2 "TP-038" TP1_PD40_D0.5_S50#1 2625,1780 r90 top (schematic designator TP40)
TP3 "TP-038" TP1_PD40_D0.5_S50#1 2000,1690 r90 top (schematic designator TP45)
TP4 "TP1_PD40_D0.5_S50" TP1_PD40_D0.5_S50#1 1505,1650 r0 top (schematic designator TP6)
TP5 "TP-038" TP1_PD40_D0.5_S50#1 2630,1635 r90 top (schematic designator TP39)
TP6 "TP-038" TP1_PD40_D0.5_S50#1 1758,1475 r90 top (schematic designator TP16)
TP7 "TP1_PD40_D0.5_S50" TP1_PD40_D0.5_S50#1 185,1455 r270 top (schematic designator TP3)
TP8 "TP1_PD40_D0.5_S50" TP1_PD40_D0.5_S50#1 535,1325 r0 top (schematic designator TP9)
TP9 "TP-038" TP1_PD40_D0.5_S50#1 2625,1290 r90 top (schematic designator TP42)
TP10 "TP-038" TP1_PD40_D0.5_S50#1 1455,1290 r180 top (schematic designator TP2)
TP11 "TP-038" TP1_PD40_D0.5_S50#1 2630,1145 r90 top (schematic designator TP41)
TP12 "TP-040_RND" TP1_PD40_D0.5_S50#1 125,1130 r180 top
TP13 "TP1_PD40_D0.5_S50" TP1_PD40_D0.5_S50#1 1870,996 r0 top (schematic designator TP1)
TP14 "TP1_PD40_D0.5_S50" TP1_PD40_D0.5_S50#1 1463,860 r0 top (schematic designator TP10)
TP15 "TP-040_RND" TP1_PD40_D0.5_S50#1 189,812 r90 top (schematic designator TP19)
TP16 "TP-038" TP1_PD40_D0.5_S50#1 1225,670 r90 top (schematic designator TP28)
TP17 "TP-040_RND" TP1_PD40_D0.5_S50#2 65,586 r90 top (schematic designator TP8)
TP18 "TP1_PD40_D0.5_S50" TP1_PD40_D0.5_S50#3 1460,495 r180 top (schematic designator TP13)
TP19 "TP1_PD40_D0.5_S50" TP1_PD40_D0.5_S50#1 500,488 r0 top (schematic designator TP7)
TP20 "TP-038" TP1_PD40_D0.5_S50#1 1490,440 r90 top (schematic designator TP43)
TP21 "TP-040_RND" TP1_PD40_D0.5_S50#1 545,400 r90 top (schematic designator TP24)
TP22 "TP-038" TP1_PD40_D0.5_S50#3 1720,395 r90 top (schematic designator TP44)
TP23 "TP1_PD40_D0.5_S50" TP1_PD40_D0.5_S50#3 1585,367.5 r180 top (schematic designator TP15)
TP24 "TP-038" TP1_PD40_D0.5_S50#3 1665,367.5 r90 top (schematic designator TP22)
TP25 "TP-038" TP1_PD40_D0.5_S50#3 1750,225 r90 top (schematic designator TP46)
TP26 "TP1_PD40_D0.5_S50" TP1_PD40_D0.5_S50#1 1103,165 r90 top (schematic designator TP5)
TP27 "TP1_PD40_D0.5_S50" TP1_PD40_D0.5_S50#1 1160,125 r90 top (schematic designator TP11)
TP28 "TP1_PD40_D0.5_S50" TP1_PD40_D0.5_S50#2 2930,90 r90 top (schematic designator TP38)
U1 "TPS7A3001DGNR" MSOP8(DGN) 1630,1833.2 r180 top (schematic designator U12)
U2 "DAC8760IPWP" PWP24-DIE84X166 2405,1620 r0 top (schematic designator U1)
U3 "LM5017MRE/NOPB" DDA0008B_N 625,1640 r270 top
U4 "OPA188AIDBVT" DBV0005A_L 2900,1545 r180 top (schematic designator U17)
U5 "DAC8760IPWP" PWP24-DIE84X166 2405,1130 r0 top (schematic designator U19)
U6 "TPS7A4700RGW" RGW0020A 1755,1115 r270 top (schematic designator U13)
U7 "OPA188AIDBVT" DBV0005A_L 2900,1105 r180 top (schematic designator U18)
U8 "TLP3123(F)" SOIC254P700X210-4N 2760,885 r0 top (schematic designator U15)
U9 "LM5069MM-2/NOPB" MUB10A_N 325,885 r0 top (schematic designator U16)
U10 "TLP3123(F)" SOIC254P700X210-4N 2760,670 r0 top (schematic designator U9)
U11 "TPS7A1650DGNR" DGN_8P 1375.6,614.2 r0 top (schematic designator U14)
U12 "TPS70933DBVT" DBV0005A_N 600,640 r270 top (schematic designator U6)
U13 "ADS8688DBT" DBT0038A_M 2105,515 r90 top (schematic designator U5)
U14 "TLP3123(F)" SOIC254P700X210-4N 2760,455 r0 top (schematic designator U10)
U15 "ISO7141CCDBQ" DBQ0016A_N 915,405 r0 top (schematic designator U11)
U16 "TLP3123(F)" SOIC254P700X210-4N 2760,235 r0 top (schematic designator U8)
U17 "SN74HC595PW" PW16 1540,195 r180 top (schematic designator U4)
U18 "ISO1541D" D0008A_N 910,150 r0 top (schematic designator U2)
U19 "AT24C02C-SSHM-B" SOIC-8 510,225 r90 top
ZZ1 "This Assembly Note is for PCB labels only" AssemblyNoteLabel 345,2460 r0 top
ZZ2 "These assemblies are ESD sensitive, ESD precautions shall be observed." AssemblyNote 347,2375.11 r0 top
ZZ3 "These assemblies must be clean and free from flux and all contaminants. Use of no clean flux is not acceptable." AssemblyNote 347,2286.56 r0 top
ZZ4 "These assemblies must comply with workmanship standards IPC-A-610 Class 2, unless otherwise specified." AssemblyNote 347,2198 r0 top

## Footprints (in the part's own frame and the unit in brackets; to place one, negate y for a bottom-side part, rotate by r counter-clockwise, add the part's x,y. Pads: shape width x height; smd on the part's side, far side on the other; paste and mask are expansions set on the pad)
0402 [mm] "0402 from SM-752 data"
  rect 0.8x0.6 smd: 1(-0.6,0) 2(0.6,0)
  silkscreen extent -1.22,-0.52 1.22,0.52, body extent -0.55,-0.3 0.55,0.3, height 0.6
0603 [mm] "0603 from SM-752 data"
  rect 1x0.95 smd: 1(-0.8,0) 2(0.8,0)
  silkscreen extent -1.52,-0.69 1.52,0.69, body extent -0.87,-0.47 0.87,0.47, height 0.85
0805 [mm] "0805 from SM-752 data"
  rect 1.3x1.5 smd: 1(-0.85,0) 2(0.85,0)
  silkscreen extent -1.72,-0.97 1.72,0.97, body extent -1.1,-0.72 1.1,0.72, height 1.1
0805_HV [mil] "0805 with 30mil clearance between pads"
  rect 50x63 smd: 1(-40,0) 2(40,0)
  silkscreen extent -74,-40 74,40, body extent -43,-29 43,29, height 43
1206 [mm] "1206 from SM-752 data"
  rect 1.3x1.85 smd: 1(-1.45,0) 2(1.45,0)
  silkscreen extent -2.4,-1.21 2.4,1.21, body extent -1.7,-0.9 1.7,0.9, height 1.35
1210#1 [mm] "1210 from SM-752 data"
  rect 1.3x2.7 smd: 1(-1.45,0) 2(1.45,0)
  silkscreen extent -2.32,-1.57 2.32,1.57, body extent -1.7,-1.35 1.7,1.35, height 1.35
1210#2 [mm]
  rect 1.27x2.794 smd: 1(1.524,0) 2(-1.524,0)
  silkscreen extent -2.54,-1.78 2.54,1.78
AssemblyNote [mil] "Assembly Note"
AssemblyNoteLabel [mil] "Assembly Note for PCB Labels"
CONN_1725711 [mm] "Phoenix Contact"
  rect 1.78x1.78 hole 1.1: 1(-8.89,0)
  round 1.78 hole 1.1: 2(-6.35,0) 3(-3.81,0) 4(-1.27,0) 5(1.27,0) 6(3.81,0) 7(6.35,0) 8(8.89,0)
  silkscreen extent -10.4,-3.1 10.4,3.1, body extent -10.39,-3.1 10.39,3.1, height 8.52
CONN_ERF8-025-05_0-L-DV-L-TR [mm] "Samtec 25X2 Header"
  rect 0.5x1.1 smd mask+0: 1(9.6,2.25) 2(9.6,-2.25) 3(8.8,2.25) 4(8.8,-2.25) 5(8,2.25) 6(8,-2.25) 7(7.2,2.25) 8(7.2,-2.25) 9(6.4,2.25) 10(6.4,-2.25) 11(5.6,2.25) 12(5.6,-2.25) 13(4.8,2.25) 14(4.8,-2.25) 15(4,2.25) 16(4,-2.25) 17(3.2,2.25) 18(3.2,-2.25) 19(2.4,2.25) 20(2.4,-2.25) 21(1.6,2.25) 22(1.6,-2.25) 23(0.8,2.25) 24(0.8,-2.25) 25(0,2.25) 26(0,-2.25) 27(-0.8,2.25) 28(-0.8,-2.25) 29(-1.6,2.25) 30(-1.6,-2.25) 31(-2.4,2.25) 32(-2.4,-2.25) 33(-3.2,2.25) 34(-3.2,-2.25) 35(-4,2.25) 36(-4,-2.25) 37(-4.8,2.25) 38(-4.8,-2.25) 39(-5.6,2.25) 40(-5.6,-2.25) 41(-6.4,2.25) 42(-6.4,-2.25) 43(-7.2,2.25) 44(-7.2,-2.25) 45(-8,2.25) 46(-8,-2.25) 47(-8.8,2.25) 48(-8.8,-2.25) 49(-9.6,2.25) 50(-9.6,-2.25)
  round 1.4 hole 0.838: MH1(12.9,0) MH2(-12.9,0)
  round 1 hole 1.45 unplated mask+0.508: MH3(11.4,-1.5) MH4(-11.4,-1.5)
  silkscreen extent -13,-3.05 13,3.05, body extent -13.03,-2.8 13.03,2.8, height 5.3
D0008A_N [mm] "SOIC, 8-Leads, Body 4.9x3.9mm, Pitch 1.27mm, IPC Medium Density"
  oval 2.2x0.6 smd: 1(-2.4,1.905) 2(-2.4,0.635) 3(-2.4,-0.635) 4(-2.4,-1.905) 5(2.4,-1.905) 6(2.4,-0.635) 7(2.4,0.635) 8(2.4,1.905)
  silkscreen extent -2.92,-2.5 0.9,2.79, body extent -2,-2.5 2,2.5, height 1.75
DBQ0016A_N [mm] "SOP, 16-Leads, Body 4.9x3.9mm, Pitch 0.635mm, IPC Medium Density"
  oval 1.95x0.4 smd: 1(-2.525,2.222) 2(-2.525,1.587) 3(-2.525,0.953) 4(-2.525,0.318) 5(-2.525,-0.318) 6(-2.525,-0.953) 7(-2.525,-1.587) 8(-2.525,-2.222) 9(2.525,-2.222) 10(2.525,-1.587) 11(2.525,-0.953) 12(2.525,-0.318) 13(2.525,0.318) 14(2.525,0.953) 15(2.525,1.587) 16(2.525,2.222)
  silkscreen extent -2.65,-2.5 1.2,3.1, body extent -1.99,-2.5 2,2.5, height 1.76
DBT0038A_M [mm]
  oval 2.05x0.3 smd: 1(-2.825,4.5) 2(-2.825,4) 3(-2.825,3.5) 4(-2.825,3) 5(-2.825,2.5) 6(-2.825,2) 7(-2.825,1.5) 8(-2.825,1) 9(-2.825,0.5) 10(-2.825,0) 11(-2.825,-0.5) 12(-2.825,-1) 13(-2.825,-1.5) 14(-2.825,-2) 15(-2.825,-2.5) 16(-2.825,-3) 17(-2.825,-3.5) 18(-2.825,-4) 19(-2.825,-4.5) 20(2.825,-4.5) 21(2.825,-4) 22(2.825,-3.5) 23(2.825,-3) 24(2.825,-2.5) 25(2.825,-2) 26(2.825,-1.5) 27(2.825,-1) 28(2.825,-0.5) 29(2.825,0) 30(2.825,0.5) 31(2.825,1) 32(2.825,1.5) 33(2.825,2) 34(2.825,2.5) 35(2.825,3) 36(2.825,3.5) 37(2.825,4) 38(2.825,4.5)
  silkscreen extent -2.95,-4.9 1.4,5.32, body extent -2.25,-4.9 2.25,4.9, height 1.2
DBV0005A_L [mm] "SOT23, 5-Leads, Body 2.9x1.6mm, Pitch 0.95mm, Lead Span 2.8mm, IPC High Density"
  rect 0.9x0.65 smd: 1(-1.2,0.95) 2(-1.2,0) 3(-1.2,-0.95) 4(1.2,-0.95) 5(1.2,0.95)
  silkscreen extent -0.35,-1.55 0.35,1.55, body extent -1.42,-1.46 1.42,1.46, height 1.08
DBV0005A_N [mm] "SOT23, 5-Leads, Body 2.9x1.6mm, Pitch 0.95mm, Lead Span 2.8mm, IPC Medium Density"
  rect 1.1x0.65 smd: 1(-1.2,0.95) 2(-1.2,0) 3(-1.2,-0.95) 4(1.2,-0.95) 5(1.2,0.95)
  silkscreen extent -0.25,-1.55 0.25,1.55, body extent -1.42,-1.46 1.42,1.46, height 1.08
DDA0008B_N [mm] "SOIC, 8-Leads, Body 4.9x3.9mm, Pitch 1.27mm, Exposed Pad, IPC Medium Density"
  oval 2x0.6 smd: 1(-2.5,1.905) 2(-2.5,0.635) 3(-2.5,-0.635) 4(-2.5,-1.905) 5(2.5,-1.905) 6(2.5,-0.635) 7(2.5,0.635) 8(2.5,1.905)
  rect 2.41x3.1 smd: 9(0,0)
  silkscreen extent -2.62,-2.5 1.1,2.88, body extent -2,-2.5 2,2.5, height 1.68
DGN_8P [mil]
  rect 40x17 smd: 1(-82.1,40) 2(-82.1,14.4) 3(-82.1,-11.2) 4(-82.1,-36.8) 5(82.9,-36.9) 6(82.9,-11.3) 7(82.9,14.3) 8(82.9,40)
  rect 80x80 smd: 9(0.2,1.4)
  silkscreen extent -106,63 -81,88
DIO_SMB_BIAAAA [mm]
  rect 2.5x2.3 smd: 1(-2.15,0) 2(2.15,0)
  silkscreen extent -2.28,-1.97 2.29,1.97
FB0603 [mm]
  rect 0.95x1 smd: 1(-0.75,0) 2(0.75,0)
  silkscreen extent -0.8,-0.7 0.8,0.7
FID_TOP_40_80BA [mil]
  round 40 smd mask+20: 1(0,0)
  Top Layer keep-out region: 45,0 41.57,17.22 31.82,31.82 17.22,41.57 0,45 0,45 -17.22,41.57 -31.82,31.82 -41.57,17.22 -45,0 -45,0 -41.57,-17.22 -31.82,-31.82 -17.22,-41.57 0,-45 0,-45 17.22,-41.57 31.82,-31.82 41.57,-17.22 45,0
IND_B82422H [mm]
  rect 1.15x2.7 smd: 1(-1.625,0) 2(1.625,0)
  Top Layer keep-out region: -0.508,-1.136 0.508,-1.136 0.508,1.13 -0.508,1.13
  silkscreen extent -1.6,-1.57 1.6,1.57, body extent -1.6,-1.25 1.6,1.25, height 2.4
Label_650x200 [mil] "Thermal Transfer Label"
  silkscreen extent -325,-100 325,100, body extent -326,-101 326,101, height 1
LED0603AA [mil]
  rect 32x32 smd: 1(-32.48,0) 2(32.48,0)
  silkscreen extent -132,-25 11,25
MH3.2_H5_W6_KO8_STARHEAD [mil]
  round 20 / inner round 142 / far side round 20 hole 128 unplated mask+65: 1(0,0)
  Keep-Out Layer region: 160,0 147.82,61.23 113.14,113.14 61.23,147.82 0,160 0,160 -61.23,147.82 -113.14,113.14 -147.82,61.23 -160,0 -160,0 -147.82,-61.23 -113.14,-113.14 -61.23,-147.82 0,-160 0,-160 61.23,-147.82 113.14,-113.14 147.82,-61.23 160,0
  silkscreen extent -120,-120 120,120
MSOP8(DGN) [mil]
  rect 50x15 smd: 1(-77,38) 2(-77,12.4) 3(-77,-13.2) 4(-77,-38.8) 5(76.6,-38.8) 6(76.6,-13.2) 7(76.6,12.4) 8(76.6,38)
  rect 60x75 smd: 9(0,-0.8)
  silkscreen extent -140,77 -115,102
MUB10A_N [mm] "TSSOP, 10-Leads, Body 3x3mm, Pitch 0.5mm, IPC Medium Density"
  oval 1.7x0.3 smd: 1(-2.05,1) 2(-2.05,0.5) 3(-2.05,0) 4(-2.05,-0.5) 5(-2.05,-1) 6(2.05,-1) 7(2.05,-0.5) 8(2.05,0) 9(2.05,0.5) 10(2.05,1)
  silkscreen extent -2.17,-1.6 0.8,1.82, body extent -1.6,-1.6 1.6,1.6, height 1.09
"NY PMS 440 0025 PH" [mil] "4-40 nylon screw and mounting hole"
  round 240 hole 128: 1(0,0)
  body extent -130,-130 130,130, height 106
powerDI123 [mm] "Diodes Inc recommended land pattern, document number DS30628 Rev. 6-2"
  rect 2.2x1.4 smd: 1(-1.275,0)
  rect 0.9x1.4 smd: 2(1.275,0)
  silkscreen extent -3.1,-1.09 1.76,1.09, body extent -2.38,-0.97 1.52,0.96, height 1
PW16 [mil]
  rect 70x15 smd: 1(-107.3,88) 2(-107.3,62.4) 3(-107.3,36.8) 4(-107.3,11.2) 5(-107.3,-14.4) 6(-107.3,-40) 7(-107.3,-65.6) 8(-107.3,-91.2) 9(111.7,-91.3) 10(111.7,-65.7) 11(111.7,-40.1) 12(111.7,-14.5) 13(111.7,11.1) 14(111.7,36.7) 15(111.7,62.3) 16(111.7,88)
  silkscreen extent -160,125 -130,155
PWP24-DIE84X166 [mil]
  rect 70x15 smd: 1(-109.3,140.5) 2(-109.3,114.9) 3(-109.3,89.3) 4(-109.3,63.7) 5(-109.3,38.1) 6(-109.3,12.5) 7(-109.3,-13.1) 8(-109.3,-38.7) 9(-109.3,-64.3) 10(-109.3,-89.9) 11(-109.3,-115.5) 12(-109.3,-141.1) 13(109.7,-141.2) 14(109.7,-115.6) 15(109.7,-90) 16(109.7,-64.4) 17(109.7,-38.8) 18(109.7,-13.2) 19(109.7,12.4) 20(109.7,38) 21(109.7,63.6) 22(109.7,89.2) 23(109.7,114.8) 24(109.7,140.5)
  rect 84x166 smd: 25(0,-0.1)
  silkscreen extent -189,190 -149,230
RGW0020A [mm] "QFN, 20-Leads, Body 5x5mm, Pitch 0.65mm, Thermal Pad 3.15x3.15mm, TI Recommended"
  oval 0.75x0.3 smd mask+0.07: 1(-2.325,1.3) 2(-2.325,0.65) 3(-2.325,0) 4(-2.325,-0.65) 5(-2.325,-1.3) 11(2.325,-1.3) 12(2.325,-0.65) 13(2.325,0) 14(2.325,0.65) 15(2.325,1.3)
  oval 0.3x0.75 smd mask+0.07: 6(-1.3,-2.325) 7(-0.65,-2.325) 8(0,-2.325) 9(0.65,-2.325) 10(1.3,-2.325) 16(1.3,2.325) 17(0.65,2.325) 18(0,2.325) 19(-0.65,2.325) 20(-1.3,2.325)
  rect 3.15x3.15 smd paste-1.575 mask+0.07: 21(0,0)
  silkscreen extent -2.73,1.88 -1.88,2.73, body extent -2.58,-2.57 2.57,2.58, height 1.01
SOD-123 [mm] "On Semi recommended land pattern"
  rect 0.915x1.22 smd: 1(-1.637,0) 2(1.637,0)
  silkscreen extent -2.75,-1.16 2.03,1.17, body extent -1.93,-0.9 1.93,0.9, height 1.35
SOD-123F [mm] "NXP recommended land pattern"
  rect 1.2x1.2 smd: 1(-1.4,0) 2(1.4,0)
  silkscreen extent -2.64,-1.12 2.01,1.12, body extent -1.8,-0.85 1.8,0.85, height 1.2
sod-323 [mm] "NXP recommended land pattern"
  rect 0.6x0.6 smd: 1(-1.1,0) 2(1.1,0)
  silkscreen extent -2.06,-0.86 1.53,0.86, body extent -1.3,-0.67 1.3,0.68, height 1.1
SOD-523 [mm] "NXP Semiconductor recommended land pattern, nominal STEP model"
  rect 0.8x0.6 smd: 1(-0.55,0) 2(0.55,0)
  silkscreen extent -1.6,-0.64 1.2,0.63, body extent -0.8,-0.4 0.8,0.4, height 0.72
SOIC254P700X210-4N [mm]
  oval 1.8x0.6 smd: 1(-3.15,1.27) 2(-3.15,-1.27) 3(3.15,-1.27) 4(3.15,1.27)
  silkscreen extent -3.43,-1.95 1.92,2.51, body extent -2.2,-1.95 2.2,1.95, height 2.1
SOIC-8 [mm] "duplicate of SO-8.  SOIC, 8-Leads, Body 5.0x4.0mm (max), Pitch 1.27mm, IPC Medium Density"
  oval 2.2x0.6 smd: 1(-2.4,1.905) 2(-2.4,0.635) 3(-2.4,-0.635) 4(-2.4,-1.905) 5(2.4,-1.905) 6(2.4,-0.635) 7(2.4,0.635) 8(2.4,1.905)
  silkscreen extent -0.9,-2.5 0.9,2.5, body extent -3,-2.45 3,2.45, height 1.63
SOT-323 [mm] "Zetex recommended land pattern.  March 2007"
  rect 0.8x0.6 smd: 1(-0.8,0.65) 2(-0.8,-0.65) 3(0.8,0)
  silkscreen extent -1.14,-1.22 1.09,1.65, body extent -1.13,-1.13 1.12,1.12, height 1.13
TEC_282834-2 [mm] "TEC"
  rect 1.6x1.6 hole 1.1: 1(-1.27,0)
  round 1.6 hole 1.1: 2(1.27,0)
  silkscreen extent -3.66,-3.4 2.9,3.4, body extent -2.77,-3.25 2.77,3.25, height 10.01
TEC_282834-4 [mm] "TEC"
  rect 1.6x1.6 hole 1.1: 1(-3.81,0)
  round 1.6 hole 1.1: 2(-1.27,0) 3(1.27,0) 4(3.81,0)
  silkscreen extent -6.2,-3.4 5.44,3.4, body extent -5.31,-3.25 5.31,3.25, height 10.02
TI_Stacked_SolderMask_Small [mil]
  silkscreen extent -418,-98 418,98
TP1_PD40_D0.5_S50#1 [mil]
  round 40 hole 20: 1(0,0)
  silkscreen extent -25,-25 25,25
TP1_PD40_D0.5_S50#2 [mil]
  round 60 hole 40: 1(0,0)
  silkscreen extent -45,-45 45,45
TP1_PD40_D0.5_S50#3 [mil]
  round 30 hole 16: 1(0,0)
  silkscreen extent -25,-25 25,25
TRANS_NexFET_Q5A [mm] "TI recommended land pattern (nominal) M0139-01"
  rect 0.75x0.675 smd: 1(-2.776,1.917) 2(-2.776,0.639) 3(-2.776,-0.639) 4(-2.776,-1.917)
  rect 0.655x0.675 smd: 5(2.776,-1.917) 6(2.776,-0.639) 7(2.776,0.639) 8(2.776,1.917)
  rect 4.295x4.51 smd paste-2.2: 9(0.301,0)
  silkscreen extent -3.4,-2.8 3.4,2.8, body extent -3.05,-2.5 3.05,2.5, height 1.11
WURTH_750313995 [mm] "WURTH"
  rect 1.17x1.88 smd: 1(-4.96,8.18) 2(-2.48,8.18) 3(0,8.18) 4(2.48,8.18) 5(4.96,8.18) 6(4.96,-8.18) 7(2.48,-8.18) 8(0,-8.18) 9(-2.48,-8.18) 10(-4.96,-8.18)
  silkscreen extent -6.7,-7.5 6.7,8.5, body extent -6.73,-8.9 6.73,8.9, height 12.7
